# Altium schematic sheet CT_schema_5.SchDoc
size 218 x 258 mm
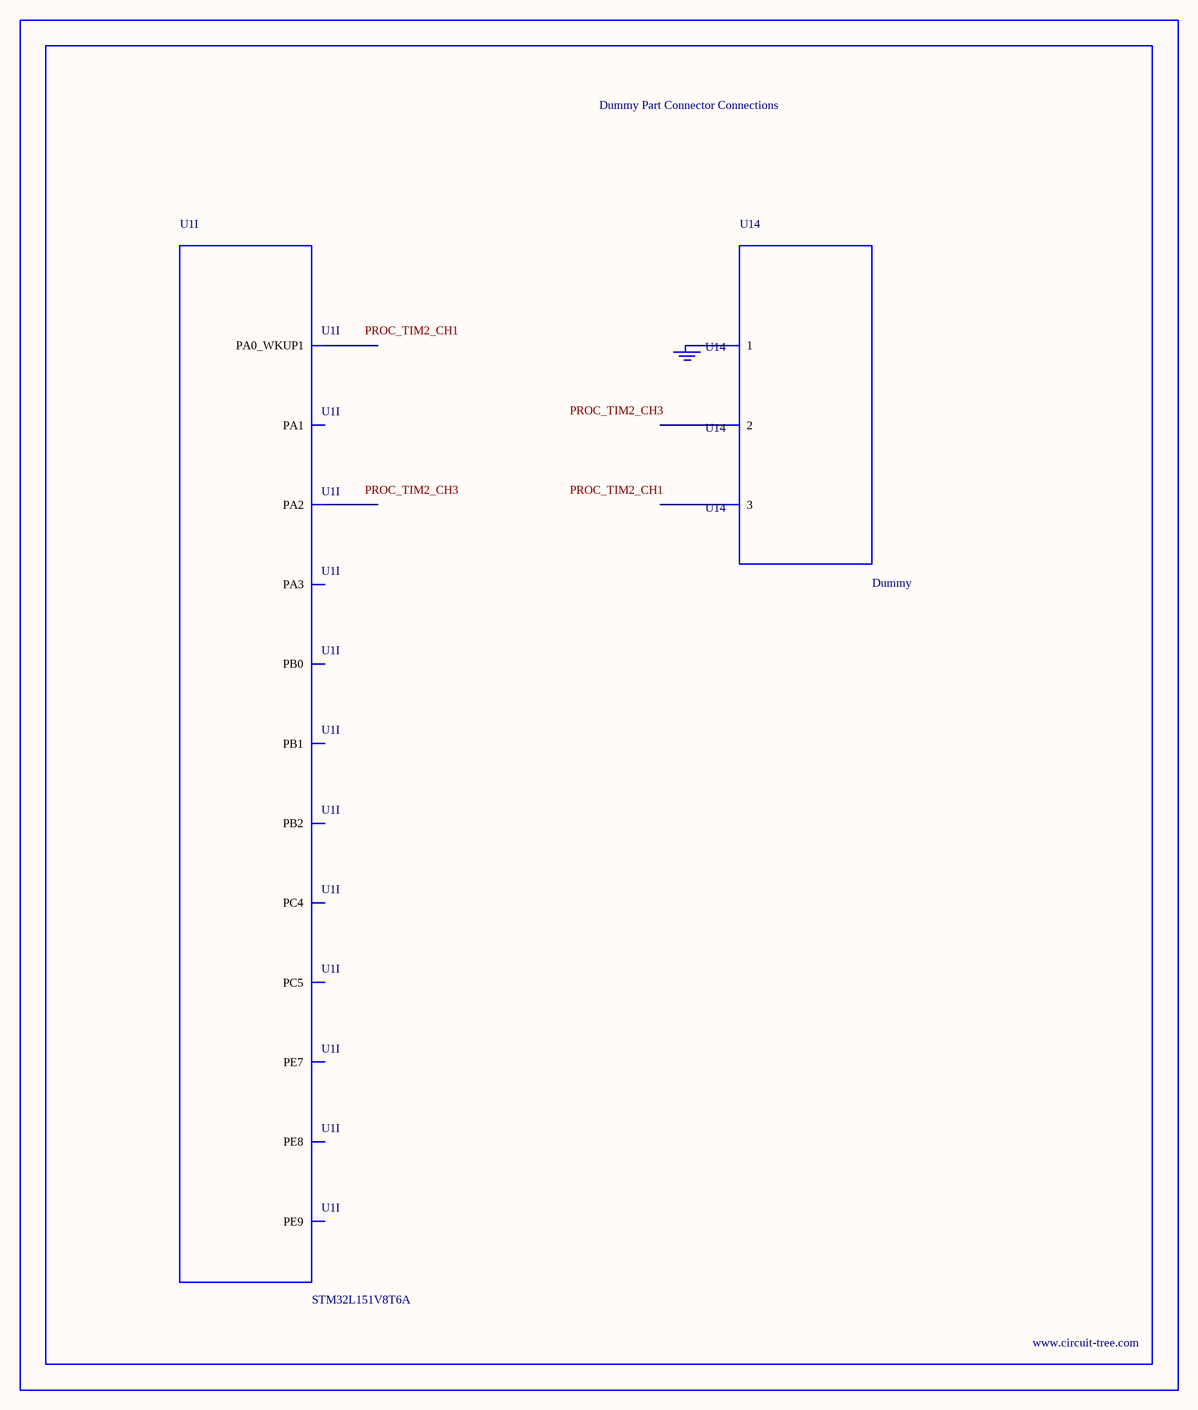
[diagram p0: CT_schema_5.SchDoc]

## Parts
BORDER4  (no value)
GND_INSTANCE_4_0  (no value)
U1  STM32L151V8T6A  [LQFP100]  (part I of 9)
U14  Dummy  [DUMMY_PACKAGE_135]

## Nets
NetGND_INSTANCE_4_0_0: GND_INSTANCE_4_0.0(GND) U14.1

Not connected (* = marked no-connect by the designer): U1 23(PA0_WKUP1) 24(PA1) 25(PA2) 26(PA3) 33(PC4) 34(PC5) 35(PB0) 36(PB1) 37(PB2) 38(PE7) 39(PE8) 40(PE9); U14 2 3

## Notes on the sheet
- Labels drawn without touching a wire or pin: PROC_TIM2_CH1, PROC_TIM2_CH3

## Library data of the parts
BORDER4 = BORDER_PAGE4
GND_INSTANCE_4_0 = GND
